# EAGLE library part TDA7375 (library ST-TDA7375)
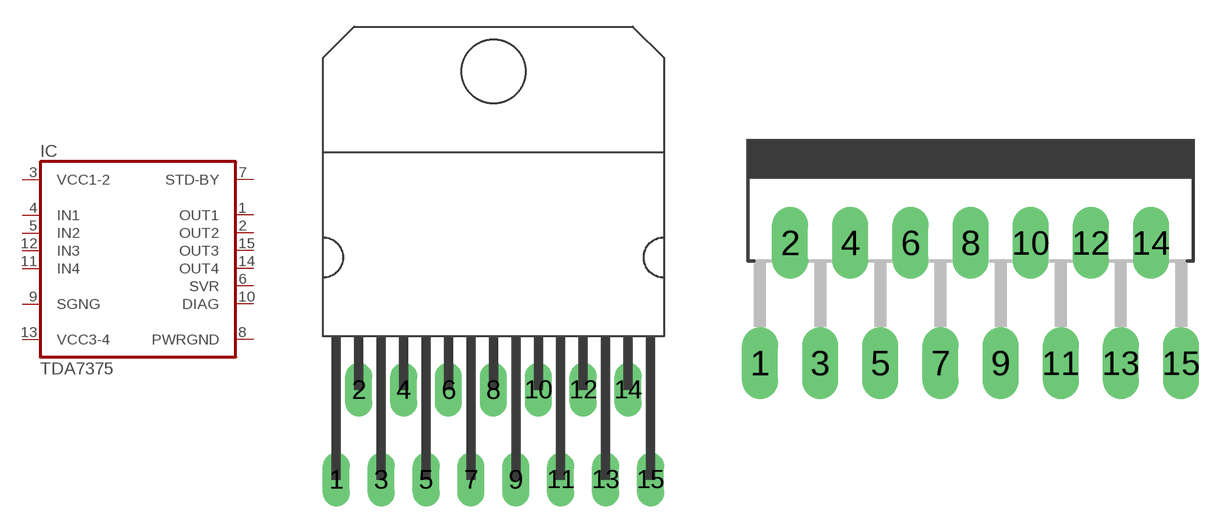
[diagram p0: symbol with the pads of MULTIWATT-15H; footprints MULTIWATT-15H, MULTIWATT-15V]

Designator prefix IC

## TDA7375H  [MULTIWATT-15H]
1  OUT1  out
2  OUT2  out
3  VCC1-2  pwr
4  IN1  in
5  IN2  in
6  SVR  pas
7  STD-BY  in
8  PWRGND  pwr
9  SGNG  pwr
10  DIAG  pas
11  IN4  in
12  IN3  in
13  VCC3-4  pwr
14  OUT4  out
15  OUT3  out

## TDA7375V  [MULTIWATT-15V]
Pads as for MULTIWATT-15H

## Footprint MULTIWATT-15H (pad centres in mm)
drill 1.016 long: 1 -8.89,-5.08; 2 -7.62,0; 3 -6.35,-5.08; 4 -5.08,0; 5 -3.81,-5.08; 6 -2.54,0; 7 -1.27,-5.08; 8 0,0; 9 1.27,-5.08; 10 2.54,0; 11 3.81,-5.08; 12 5.08,0; 13 6.35,-5.08; 14 7.62,0; 15 8.89,-5.08

## Footprint MULTIWATT-15V (pad centres in mm)
drill 1.016 long: 1 -8.89,-7.62; 2 -7.62,-2.54; 3 -6.35,-7.62; 4 -5.08,-2.54; 5 -3.81,-7.62; 6 -2.54,-2.54; 7 -1.27,-7.62; 8 0,-2.54; 9 1.27,-7.62; 10 2.54,-2.54; 11 3.81,-7.62; 12 5.08,-2.54; 13 6.35,-7.62; 14 7.62,-2.54; 15 8.89,-7.62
